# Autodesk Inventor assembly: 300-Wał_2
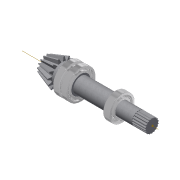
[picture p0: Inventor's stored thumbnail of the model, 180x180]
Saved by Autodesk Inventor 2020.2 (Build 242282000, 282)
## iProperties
Created: 2015-05
Part Number: 300-Wał_2
Document SubType Name: Assembly
Designer: F.Stasiak
Manager: www.cadconsulting.pl
Company: Fabian Stasiak CAD Consulting
Author: F.Stasiak
Subject: Zbiór ćwiczeń. Autodesk Inventor 2020. Kurs podstawowy
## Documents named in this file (5)
- C:\2020_Kurs_podstawowy\R7 Prezentacje\Komponenty\300-Wał_2.iam
- C:\2020_Kurs_podstawowy\R7 Prezentacje\Komponenty\V_SKF 61907.ipt
- C:\2020_Kurs_podstawowy\R7 Prezentacje\Komponenty\V_SKF 6005.ipt
- C:\2020_Kurs_podstawowy\R7 Prezentacje\Komponenty\V_123-0030.ipt
- C:\2020_Kurs_podstawowy\R7 Prezentacje\Komponenty\V_123-0090.ipt
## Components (5 placed, 4 different names)
1. Łożysko SKF 61907:1
2. Łożysko SKF 61907:2
3. Łożysko SKF 6005:1
4. Przekładnie zębate stożkowe 15/51, 3:1
5. V_123-0090:1
